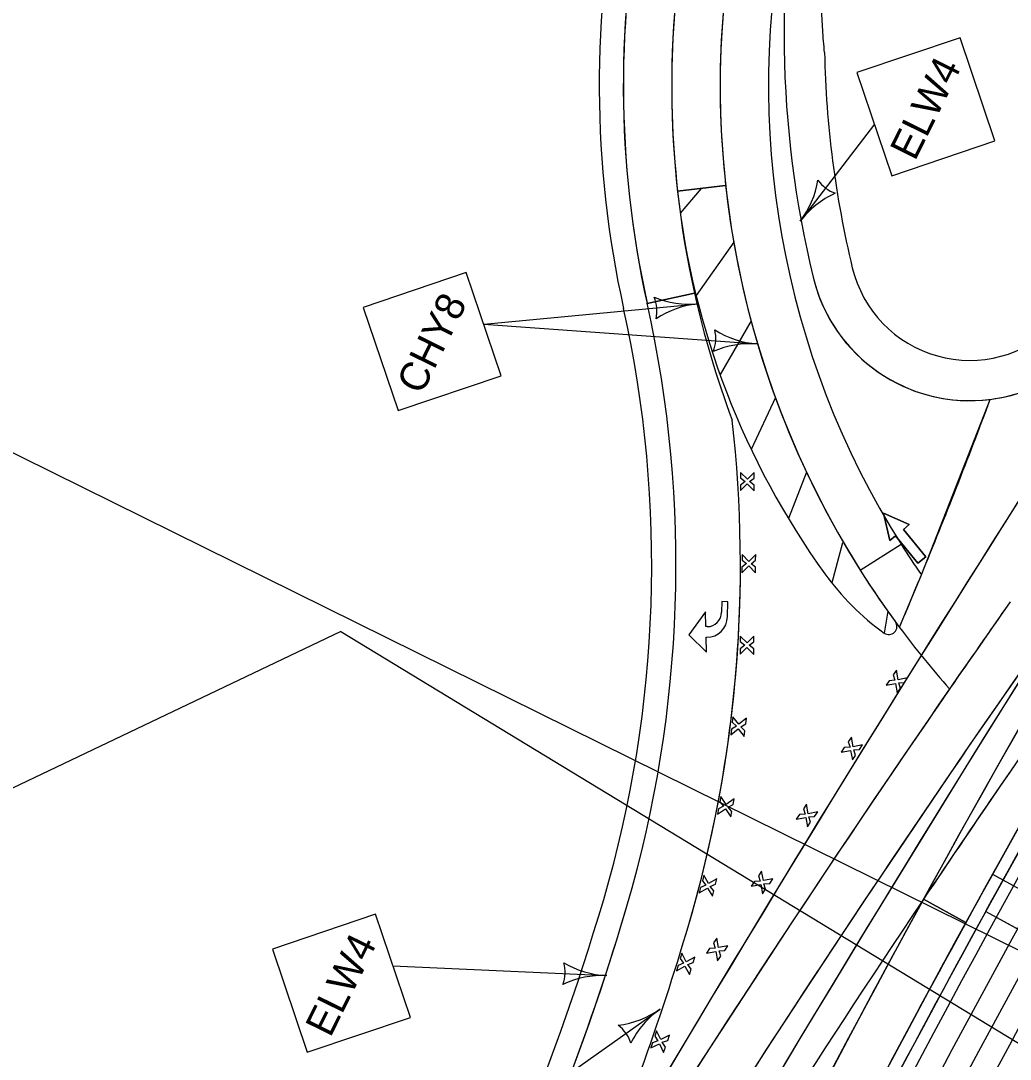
# Model space of a CAD drawing. Extents: x 14104283 to 14120882, y 8635219 to 8671666.
# Drawn here: x 14118835.2 to 14119080.6, y 8668695.1 to 8668952.7 of the extents above; entities that cross this region are included whole.
import ezdxf

# ---------------------------------------------------------------- set-up
doc = ezdxf.new("R2010")
doc.units = 0
for name, color, linetype in [('Cell', 7, 'Continuous'), ('dsnNonPlotable', 7, 'Continuous'), ('dsnPaintExistingStopLineWhite', 7, 'Continuous'), ('dsnPaintPlaceBrokenLineWhite', 7, 'Continuous'), ('dsnPaintPlaceChannelizingLaneWhite', 7, 'Continuous'), ('dsnPaintPlaceChannelizingLaneYellow', 7, 'Continuous'), ('dsnPaintPlaceEdgeLineLeftYellow', 7, 'Continuous'), ('dsnPaintPlaceEdgeLineRightWhite', 7, 'Continuous'), ('dsnPaintPlaceLaneLineWhite', 7, 'Continuous'), ('dsnPaintPlaceNoPassingLineYellow', 7, 'Continuous'), ('dsnPaintRemoveDoubleCenterLineYellow', 7, 'Continuous'), ('dsnPaintRemoveEdgeLineWhite', 7, 'Continuous'), ('dsnShadingPaved', 7, 'Continuous'), ('dsnStdLabel', 7, 'Continuous'), ('dsnStgShadingPrevPav', 7, 'Continuous'), ('dsnTapePlaceChannelizingLaneWhite', 7, 'Continuous'), ('dsnTapePlaceChannelizingLaneYellow', 7, 'Continuous'), ('dsnTextFinalPlan', 7, 'Continuous'), ('Level 2', 7, 'Continuous'), ('Level 5', 7, 'Continuous')]:
    doc.layers.add(name, color=color, linetype=linetype)

msp = doc.modelspace()

# ---------------------------------------------------------------- linework, layer by layer
at = {"layer": 'Cell'}
for p, q in [((14119013.7, 8668840.65), (14119013.69, 8668839.27)), ((14119013.69, 8668839.27), (14119014.8, 8668838.39)), ((14119015.37, 8668838.95), (14119013.7, 8668840.65)), ((14119017.07, 8668840.62), (14119015.37, 8668838.95)), ((14119015.93, 8668838.38), (14119017.06, 8668839.25)), ((14119017.06, 8668839.25), (14119017.07, 8668840.62)), ((14119013.66, 8668836.15), (14119015.36, 8668837.82)), ((14119013.67, 8668837.52), (14119013.66, 8668836.15)), ((14119014.8, 8668838.39), (14119013.67, 8668837.52)), ((14119015.36, 8668837.82), (14119017.04, 8668836.12)), ((14119017.05, 8668837.5), (14119015.93, 8668838.38)), ((14119017.04, 8668836.12), (14119017.05, 8668837.5)), ((14119014.06, 8668820.28), (14119014.05, 8668818.9)), ((14119014.05, 8668818.9), (14119015.17, 8668818.02)), ((14119015.74, 8668818.58), (14119014.06, 8668820.28)), ((14119017.44, 8668820.25), (14119015.74, 8668818.58)), ((14119016.3, 8668818.01), (14119017.43, 8668818.88)), ((14119017.43, 8668818.88), (14119017.44, 8668820.25)), ((14119014.03, 8668815.78), (14119015.73, 8668817.45)), ((14119014.04, 8668817.15), (14119014.03, 8668815.78)), ((14119015.17, 8668818.02), (14119014.04, 8668817.15)), ((14119015.73, 8668817.45), (14119017.4, 8668815.75)), ((14119017.41, 8668817.13), (14119016.3, 8668818.01)), ((14119017.4, 8668815.75), (14119017.41, 8668817.13)), ((14119005.4, 8668802.4), (14119005.09, 8668802.41)), ((14119005.16, 8668799.78), (14119005.34, 8668799.77)), ((14119013.61, 8668800.05), (14119013.6, 8668798.68)), ((14119013.6, 8668798.68), (14119014.72, 8668797.79)), ((14119015.29, 8668798.35), (14119013.61, 8668800.05)), ((14119016.99, 8668800.03), (14119015.29, 8668798.35)), ((14119015.85, 8668797.79), (14119016.98, 8668798.65)), ((14119016.98, 8668798.65), (14119016.99, 8668800.03)), ((14119013.58, 8668795.55), (14119015.28, 8668797.23)), ((14119013.59, 8668796.93), (14119013.58, 8668795.55)), ((14119014.72, 8668797.79), (14119013.59, 8668796.93)), ((14119015.28, 8668797.23), (14119016.95, 8668795.53)), ((14119016.96, 8668796.9), (14119015.85, 8668797.79)), ((14119016.95, 8668795.53), (14119016.96, 8668796.9)), ((14119052.33, 8668791.58), (14119051.55, 8668790.45)), ((14119051.55, 8668790.45), (14119051.98, 8668789.09)), ((14119052.76, 8668789.23), (14119052.33, 8668791.58)), ((14119050.56, 8668789), (14119049.78, 8668787.87)), ((14119049.78, 8668787.87), (14119052.12, 8668788.31)), ((14119051.98, 8668789.09), (14119050.56, 8668789)), ((14119052.12, 8668788.31), (14119052.56, 8668785.96)), ((14119055.11, 8668789.67), (14119052.76, 8668789.23)), ((14119052.91, 8668788.45), (14119054.33, 8668788.53)), ((14119053.34, 8668787.09), (14119052.91, 8668788.45)), ((14119054.33, 8668788.53), (14119055.11, 8668789.67)), ((14119052.56, 8668785.96), (14119053.34, 8668787.09)), ((14119011.8, 8668780.07), (14119011.63, 8668778.7)), ((14119013.27, 8668778.19), (14119011.8, 8668780.07)), ((14119012.64, 8668777.7), (14119011.42, 8668776.96)), ((14119011.63, 8668778.7), (14119012.64, 8668777.7)), ((14119015.15, 8668779.66), (14119013.27, 8668778.19)), ((14119013.76, 8668777.56), (14119014.98, 8668778.29)), ((14119014.77, 8668776.56), (14119013.76, 8668777.56)), ((14119014.98, 8668778.29), (14119015.15, 8668779.66)), ((14119011.26, 8668775.6), (14119013.13, 8668777.07)), ((14119011.42, 8668776.96), (14119011.26, 8668775.6)), ((14119013.13, 8668777.07), (14119014.61, 8668775.19)), ((14119014.61, 8668775.19), (14119014.77, 8668776.56)), ((14119041.19, 8668774.97), (14119040.41, 8668773.84)), ((14119041.62, 8668772.62), (14119041.19, 8668774.97)), ((14119039.41, 8668772.39), (14119038.64, 8668771.26)), ((14119040.84, 8668772.48), (14119039.41, 8668772.39)), ((14119040.41, 8668773.84), (14119040.84, 8668772.48)), ((14119043.97, 8668773.06), (14119041.62, 8668772.62)), ((14119043.19, 8668771.92), (14119043.97, 8668773.06)), ((14119038.64, 8668771.26), (14119040.98, 8668771.7)), ((14119040.98, 8668771.7), (14119041.42, 8668769.35)), ((14119041.42, 8668769.35), (14119042.2, 8668770.48)), ((14119041.76, 8668771.84), (14119043.19, 8668771.92)), ((14119042.2, 8668770.48), (14119041.76, 8668771.84)), ((14119008.8, 8668760.29), (14119008.55, 8668758.93)), ((14119010.15, 8668758.31), (14119008.8, 8668760.29)), ((14119012.12, 8668759.66), (14119010.15, 8668758.31)), ((14119011.86, 8668758.3), (14119012.12, 8668759.66)), ((14119008.22, 8668757.22), (14119007.96, 8668755.86)), ((14119007.96, 8668755.86), (14119009.94, 8668757.21)), ((14119009.49, 8668757.87), (14119008.22, 8668757.22)), ((14119008.55, 8668758.93), (14119009.49, 8668757.87)), ((14119009.94, 8668757.21), (14119011.28, 8668755.23)), ((14119010.59, 8668757.66), (14119011.86, 8668758.3)), ((14119011.54, 8668756.59), (14119010.59, 8668757.66)), ((14119030.05, 8668758.36), (14119029.27, 8668757.23)), ((14119029.27, 8668757.23), (14119029.7, 8668755.87)), ((14119030.48, 8668756.01), (14119030.05, 8668758.36)), ((14119011.28, 8668755.23), (14119011.54, 8668756.59)), ((14119028.27, 8668755.79), (14119027.49, 8668754.65)), ((14119027.49, 8668754.65), (14119029.84, 8668755.09)), ((14119029.7, 8668755.87), (14119028.27, 8668755.79)), ((14119029.84, 8668755.09), (14119030.27, 8668752.74)), ((14119032.83, 8668756.45), (14119030.48, 8668756.01)), ((14119030.62, 8668755.23), (14119032.05, 8668755.31)), ((14119031.05, 8668753.87), (14119030.62, 8668755.23)), ((14119032.05, 8668755.31), (14119032.83, 8668756.45)), ((14119030.27, 8668752.74), (14119031.05, 8668753.87)), ((14119018.9, 8668741.75), (14119018.12, 8668740.62)), ((14119019.34, 8668739.4), (14119018.9, 8668741.75)), ((14119004.55, 8668740.73), (14119004.21, 8668739.39)), ((14119004.21, 8668739.39), (14119005.08, 8668738.27)), ((14119005.77, 8668738.67), (14119004.55, 8668740.73)), ((14119007.82, 8668739.89), (14119005.77, 8668738.67)), ((14119007.48, 8668738.56), (14119007.82, 8668739.89)), ((14119017.13, 8668739.18), (14119016.35, 8668738.04)), ((14119018.56, 8668739.26), (14119017.13, 8668739.18)), ((14119018.12, 8668740.62), (14119018.56, 8668739.26)), ((14119021.68, 8668739.84), (14119019.34, 8668739.4)), ((14119019.48, 8668738.62), (14119020.91, 8668738.7)), ((14119020.91, 8668738.7), (14119021.68, 8668739.84)), ((14119003.78, 8668737.7), (14119003.44, 8668736.37)), ((14119003.44, 8668736.37), (14119005.49, 8668737.58)), ((14119005.08, 8668738.27), (14119003.78, 8668737.7)), ((14119005.49, 8668737.58), (14119006.71, 8668735.53)), ((14119006.17, 8668737.99), (14119007.48, 8668738.56)), ((14119007.05, 8668736.87), (14119006.17, 8668737.99)), ((14119006.71, 8668735.53), (14119007.05, 8668736.87)), ((14119016.35, 8668738.04), (14119018.7, 8668738.48)), ((14119018.7, 8668738.48), (14119019.13, 8668736.13)), ((14119019.13, 8668736.13), (14119019.91, 8668737.26)), ((14119019.91, 8668737.26), (14119019.48, 8668738.62)), ((14119007.76, 8668725.14), (14119006.98, 8668724.01)), ((14119006.98, 8668724.01), (14119007.41, 8668722.65)), ((14119008.2, 8668722.79), (14119007.76, 8668725.14)), ((14118999.09, 8668721.38), (14118998.69, 8668720.06)), ((14119000.21, 8668719.27), (14118999.09, 8668721.38)), ((14119005.99, 8668722.57), (14119005.21, 8668721.43)), ((14119005.21, 8668721.43), (14119007.56, 8668721.87)), ((14119007.41, 8668722.65), (14119005.99, 8668722.57)), ((14119007.56, 8668721.87), (14119007.99, 8668719.52)), ((14119010.54, 8668723.23), (14119008.2, 8668722.79)), ((14119008.34, 8668722.01), (14119009.76, 8668722.09)), ((14119008.77, 8668720.65), (14119008.34, 8668722.01)), ((14119009.76, 8668722.09), (14119010.54, 8668723.23)), ((14118998.18, 8668718.39), (14118997.78, 8668717.07)), ((14118997.78, 8668717.07), (14118999.88, 8668718.2)), ((14118999.51, 8668718.9), (14118998.18, 8668718.39)), ((14118998.69, 8668720.06), (14118999.51, 8668718.9)), ((14118999.88, 8668718.2), (14119001, 8668716.09)), ((14119002.32, 8668720.4), (14119000.21, 8668719.27)), ((14119000.58, 8668718.57), (14119001.91, 8668719.08)), ((14119001.41, 8668717.41), (14119000.58, 8668718.57)), ((14119001.91, 8668719.08), (14119002.32, 8668720.4)), ((14119007.99, 8668719.52), (14119008.77, 8668720.65)), ((14119001, 8668716.09), (14119001.41, 8668717.41)), ((14118992.87, 8668702.17), (14118992.42, 8668700.87)), ((14118992.42, 8668700.87), (14118993.2, 8668699.67)), ((14118993.92, 8668700.02), (14118992.87, 8668702.17)), ((14118996.06, 8668701.07), (14118993.92, 8668700.02)), ((14118995.61, 8668699.77), (14118996.06, 8668701.07)), ((14118991.85, 8668699.21), (14118991.4, 8668697.91)), ((14118991.4, 8668697.91), (14118993.55, 8668698.96)), ((14118993.2, 8668699.67), (14118991.85, 8668699.21)), ((14118993.55, 8668698.96), (14118994.6, 8668696.81)), ((14118994.26, 8668699.31), (14118995.61, 8668699.77)), ((14118995.04, 8668698.11), (14118994.26, 8668699.31)), ((14118994.6, 8668696.81), (14118995.04, 8668698.11))]:
    msp.add_line(p, q, dxfattribs=at)
for points in [[(14119010.44, 8668804.91), (14119010.53, 8668808.59), (14119009.03, 8668808.63), (14119008.97, 8668806)], [(14119010.44, 8668804.91), (14119010.53, 8668808.59), (14119009.03, 8668808.63), (14119008.97, 8668806)], [(14119005.09, 8668802.41), (14119004.99, 8668806.09), (14119000.87, 8668800.4)], [(14119005.09, 8668802.41), (14119004.99, 8668806.09), (14119000.87, 8668800.4)], [(14119005.4, 8668802.4), (14119005.09, 8668802.41)], [(14119000.87, 8668800.4), (14119005.26, 8668796.09), (14119005.16, 8668799.78)], [(14119000.87, 8668800.4), (14119005.26, 8668796.09), (14119005.16, 8668799.78)], [(14119005.16, 8668799.78), (14119005.34, 8668799.77)]]:
    msp.add_lwpolyline(points, dxfattribs=at)
for centre, major_axis in [((14119005.49, 8668806.08), (0.08, 3.68)), ((14119005.49, 8668806.08), (0.08, 3.68)), ((14119005.46, 8668805.03), (0.12, 5.26)), ((14119005.46, 8668805.03), (0.12, 5.26))]:
    msp.add_ellipse(centre, major_axis=major_axis, ratio=0.9474, start_param=3.141593, end_param=4.712389, dxfattribs=at)
at = {"layer": 'dsnNonPlotable'}
msp.add_lwpolyline([(14118631.64, 8668945.1), (14119326.37, 8670350.23), (14120231.75, 8669902.59), (14119537.02, 8668497.46)], close=True, dxfattribs=at)
at = {"layer": 'dsnPaintExistingStopLineWhite'}
msp.add_line((14119076.21, 8668741.04), (14119097.19, 8668729.4), dxfattribs=at)
at = {"layer": 'dsnPaintPlaceBrokenLineWhite'}
for centre, radius, start, end in [((14121592.11, 8667345.68), 2864.95, 147.15737, 157.1633), ((14121955.85, 8666791.92), 3500, 144.95493, 149.50762)]:
    msp.add_arc(centre, radius, start, end, dxfattribs=at)
at = {"layer": 'dsnPaintPlaceChannelizingLaneWhite'}
for centre, radius, start, end in [((14118697.65, 8668817.62), 316, 343.6304, 0.4076), ((14118409.81, 8668902.17), 616, 336.56541, 343.63038)]:
    msp.add_arc(centre, radius, start, end, dxfattribs=at)
at = {"layer": 'dsnPaintPlaceChannelizingLaneYellow'}
for p, q in [((14118998.06, 8668910.38), (14119009.98, 8668911.83)), ((14119003.91, 8668911.1), (14118998.74, 8668904.97)), ((14119011.98, 8668897.78), (14119002.67, 8668884.54)), ((14119016.3, 8668878.26), (14119008.59, 8668864.92)), ((14119022.33, 8668859.19), (14119016.34, 8668846.32)), ((14119030.03, 8668840.74), (14119025.56, 8668829.19)), ((14119038.93, 8668823.15), (14119036.32, 8668813.23)), ((14119050.18, 8668806.25), (14119049.3, 8668800.81))]:
    msp.add_line(p, q, dxfattribs=at)
for centre, radius, start, end in [((14119233.62, 8668936.54), 225, 186.3042, 216.2139), ((14119196.84, 8668932.46), 200, 186.3366, 215.7802), ((14119087.32, 8668853.53), 65, 215.7802, 234.1997), ((14119050.47, 8668802.43), 2, 234.1997, 36.2139), ((14121592.11, 8667345.68), 2888.95, 151.25989, 155.3184)]:
    msp.add_arc(centre, radius, start, end, dxfattribs=at)
at = {"layer": 'dsnPaintPlaceEdgeLineLeftYellow'}
msp.add_arc((14121592.11, 8667345.68), 2876.95, 147.15737, 151.25989, dxfattribs=at)
at = {"layer": 'dsnPaintPlaceEdgeLineRightWhite'}
for centre, radius, start, end in [((14119284.46, 8668949.91), 260, 168.2924, 193.5302), ((14119233.62, 8668936.54), 249, 167.9329, 192.5104), ((14121592.11, 8667345.68), 2852.95, 147.15737, 157.1633), ((14119070.57, 8668898.44), 40, 193.5302, 305.9003), ((14118697.65, 8668817.62), 300, 343.6304, 12.5104), ((14118409.81, 8668902.17), 600, 334.79009, 343.63038)]:
    msp.add_arc(centre, radius, start, end, dxfattribs=at)
at = {"layer": 'dsnPaintPlaceLaneLineWhite'}
msp.add_arc((14121592.11, 8667345.68), 2876.95, 151.25989, 153.70867, dxfattribs=at)
at = {"layer": 'dsnPaintPlaceNoPassingLineYellow'}
for radius, end in [(237, 186.3366), (225, 186.3042)]:
    msp.add_arc((14119233.62, 8668936.54), radius, 167.9329, end, dxfattribs=at)
at = {"layer": 'dsnPaintRemoveDoubleCenterLineYellow'}
msp.add_arc((14121592.11, 8667345.68), 2858.95, 147.15737, 155.63386, dxfattribs=at)
at = {"layer": 'dsnPaintRemoveEdgeLineWhite'}
for centre, radius, start, end in [((14121639.53, 8667321.97), 2923.92, 146.37023, 155.59399), ((14121592.11, 8667345.68), 2846.95, 147.15737, 155.63407)]:
    msp.add_arc(centre, radius, start, end, dxfattribs=at)
at = {"layer": 'dsnShadingPaved'}
for p, q in [((14119009.98, 8668911.83), (14118998.06, 8668910.38)), ((14118990.52, 8668882.53), (14119002.23, 8668885.13)), ((14118990.53, 8668882.6), (14119002.24, 8668885.2)), ((14119058.53, 8668815.24), (14119075.63, 8668858.76)), ((14119043.37, 8668816.41), (14119053.52, 8668822.82)), ((14119043.37, 8668816.41), (14119053.52, 8668822.82)), ((14119053.1, 8668802.23), (14119058.53, 8668815.24)), ((14119059.06, 8668734.79), (14119069.58, 8668729.02)), ((14119069.58, 8668729.02), (14119059.06, 8668734.79))]:
    msp.add_line(p, q, dxfattribs=at)
for centre, radius, start, end in [((14119284.46, 8668949.91), 260, 168.2924, 193.5302), ((14119233.6, 8668936.46), 249, 167.9329, 192.5104), ((14119233.6, 8668936.46), 237, 167.9329, 192.5105), ((14119233.62, 8668936.54), 237, 167.9329, 186.3366), ((14119233.62, 8668936.54), 225, 167.9329, 212.2703), ((14119233.62, 8668936.54), 225, 167.9329, 186.3042), ((14119233.62, 8668936.54), 213, 167.9329, 212.2703), ((14119233.62, 8668936.54), 213, 167.9329, 212.2703), ((14121592.11, 8667345.68), 2876.95, 147.15737, 157.1633), ((14121592.11, 8667345.68), 2876.95, 147.15737, 151.25989), ((14121592.11, 8667345.68), 2852.95, 147.15737, 157.1633), ((14119070.57, 8668898.44), 40, 193.5302, 277.2674), ((14119233.62, 8668936.54), 237, 192.5105, 200.4779), ((14118697.65, 8668817.62), 300, 343.6304, 12.5104), ((14119070.57, 8668898.44), 40, 277.2674, 305.9003), ((14117682.33, 8669381.12), 1488, 337.64823, 339.44858), ((14118697.65, 8668817.62), 316, 343.6304, 6.5432), ((14119233.62, 8668936.54), 213, 212.2703, 214.7131), ((14119233.62, 8668936.54), 213, 212.2703, 214.7131), ((14119233.62, 8668936.54), 225, 212.2703, 216.6514), ((14117682.33, 8669381.12), 1488, 337.10525, 337.64823), ((14121955.85, 8666791.92), 3512, 144.95493, 152.69211), ((14121955.85, 8666791.92), 3512, 144.95493, 145.38458), ((14121955.85, 8666791.92), 3500, 144.95493, 152.69211), ((14121955.85, 8666791.92), 3500, 144.95493, 149.50762), ((14119233.62, 8668936.54), 225, 216.6514, 221.6647), ((14121955.85, 8666791.92), 3488, 144.95493, 149.50762), ((14121955.85, 8666791.92), 3488, 144.95493, 146.1504), ((14121592.11, 8667345.68), 2888.95, 151.25989, 155.3184), ((14118409.81, 8668902.17), 600, 330.3689, 343.63038), ((14121592.11, 8667345.68), 2876.95, 151.25989, 157.1633), ((14118409.81, 8668902.17), 616, 336.56541, 343.63038)]:
    msp.add_arc(centre, radius, start, end, dxfattribs=at)
at = {"layer": 'dsnStdLabel'}
for p, q in [((14119046.88, 8668927.01), (14119028.47, 8668902.93)), ((14118949.99, 8668877.42), (14119003.23, 8668882.46)), ((14118949.99, 8668877.42), (14119017.87, 8668872.52)), ((14118927.45, 8668718.27), (14118980.53, 8668715.87)), ((14118883.62, 8668629.6), (14118993.74, 8668707.57))]:
    msp.add_line(p, q, dxfattribs=at)
for points in [[(14119051.21, 8668914.22), (14119076.79, 8668922.87), (14119068.13, 8668948.45), (14119042.56, 8668939.8)], [(14118928.74, 8668855.98), (14118954.32, 8668864.64), (14118945.66, 8668890.21), (14118920.09, 8668881.56)], [(14118906.2, 8668696.83), (14118931.78, 8668705.48), (14118923.13, 8668731.06), (14118897.55, 8668722.4)]]:
    msp.add_lwpolyline(points, close=True, dxfattribs=at)
for centre, radius, start, end in [((14119010.24, 8668916.88), 22.95, 322.5815, 350.6528), ((14119040.16, 8668918.22), 8.86, 214.8473, 250.3158), ((14119046.69, 8668888.99), 22.95, 114.5103, 142.5817), ((14119001.07, 8668905.3), 22.95, 247.3277, 275.399), ((14118984.08, 8668880.65), 8.86, 347.6647, 23.1331), ((14119005.39, 8668859.61), 22.95, 95.3989, 123.4701), ((14118998.68, 8668873.91), 8.86, 338.1346, 13.603), ((14119019.52, 8668895.41), 22.95, 237.7976, 265.8689), ((14119016.21, 8668849.63), 22.95, 85.8687, 113.94), ((14118961.31, 8668716.73), 8.86, 339.7107, 15.1791), ((14118981.55, 8668738.79), 22.95, 239.3737, 267.445), ((14118979.51, 8668692.94), 22.95, 87.4448, 115.5161), ((14118980.48, 8668726.3), 22.95, 277.2278, 305.2991), ((14119007, 8668688.84), 22.95, 125.2989, 153.3702), ((14118978.03, 8668696.45), 8.86, 17.5648, 53.0332)]:
    msp.add_arc(centre, radius, start, end, dxfattribs=at)
at = {"layer": 'dsnStgShadingPrevPav'}
for p, q in [((14119103.24, 8668715.93), (14119074.45, 8668731.78)), ((14119074.5, 8668731.75), (14119103.24, 8668715.93))]:
    msp.add_line(p, q, dxfattribs=at)
for centre, radius, start, end in [((14119233.62, 8668936.54), 255, 167.9329, 192.5104), ((14119284.46, 8668949.91), 250, 181.1696, 193.5302), ((14123732.96, 8665874.38), 5512, 146.42562, 157.1633), ((14123732.59, 8665873.82), 5512, 146.50213, 150.36196), ((14123732.96, 8665874.38), 5488, 146.42119, 157.1633), ((14121592.11, 8667345.68), 2888.95, 147.23666, 156.23389), ((14123732.85, 8665874.2), 5488.01, 146.41277, 150.66874), ((14121592.11, 8667345.68), 2888.95, 147.23666, 155.3184), ((14121592.13, 8667345.67), 2876.95, 147.18034, 155.90343), ((14121592.11, 8667345.68), 2876.95, 147.24009, 156.23389), ((14121592.13, 8667345.67), 2873.95, 147.18114, 155.90343), ((14121591.75, 8667345.11), 2873.96, 147.23629, 151.15167), ((14119070.57, 8668898.44), 30, 193.5302, 315.2544), ((14118697.65, 8668817.62), 294, 343.6304, 12.5104), ((14118409.81, 8668902.17), 594, 330.3689, 343.63038), ((14121592.11, 8667345.68), 2873.95, 151.16499, 155.90343)]:
    msp.add_arc(centre, radius, start, end, dxfattribs=at)
msp.add_open_spline([(14119034.51, 8668944.81), (14119034.43, 8668945.74), (14119034.26, 8668947.61), (14119034.06, 8668950.43), (14119033.88, 8668953.24), (14119033.73, 8668956.06), (14119033.62, 8668958.89), (14119033.53, 8668961.71), (14119033.48, 8668964.55), (14119033.46, 8668967.38), (14119033.47, 8668970.21), (14119033.52, 8668973.05), (14119033.6, 8668975.89), (14119033.71, 8668978.73), (14119033.85, 8668981.57), (14119034.02, 8668984.41), (14119034.23, 8668987.26), (14119034.46, 8668990.1), (14119034.73, 8668992.94), (14119035.04, 8668995.78), (14119035.37, 8668998.62), (14119035.62, 8669000.51), (14119035.74, 8669001.45)], degree=3, dxfattribs=at)
at = {"layer": 'dsnTapePlaceChannelizingLaneWhite'}
msp.add_arc((14121955.85, 8666791.92), 3512, 145.38458, 147.96378, dxfattribs=at)
at = {"layer": 'dsnTapePlaceChannelizingLaneYellow'}
msp.add_arc((14121955.85, 8666791.92), 3488, 144.95493, 149.50762, dxfattribs=at)
at = {"layer": 'dsnTextFinalPlan'}
for q in [(14118745.44, 8668720.62), (14119143.05, 8668662.37)]:
    msp.add_line((14118914.55, 8668801.16), q, dxfattribs=at)
at = {"layer": 'Level 2'}
msp.add_lwpolyline([(14119057.68, 8668818.15), (14119059.62, 8668819.73), (14119054.09, 8668826.51), (14119055.54, 8668827.7), (14119049.17, 8668830.57), (14119050.7, 8668823.75), (14119052.15, 8668824.94)], close=True, dxfattribs=at)
at = {"layer": 'Level 5'}
msp.add_lwpolyline([(14119052.15, 8668824.94), (14119050.7, 8668823.75), (14119049.17, 8668830.57), (14119055.54, 8668827.7), (14119054.09, 8668826.51), (14119059.62, 8668819.73), (14119057.68, 8668818.15), (14119052.15, 8668824.94)], dxfattribs=at)

# ---------------------------------------------------------------- texts
at = {"layer": 'dsnStdLabel'}
for s, p in [('ELW4', (14119056.94, 8668917.68)), ('CHY8', (14118934.58, 8668859.67)), ('ELW4', (14118911.93, 8668700.29))]:
    msp.add_text(s, height=7.2, rotation=63.6912, dxfattribs=at).set_placement(p)

doc.saveas('drawing.dxf')
